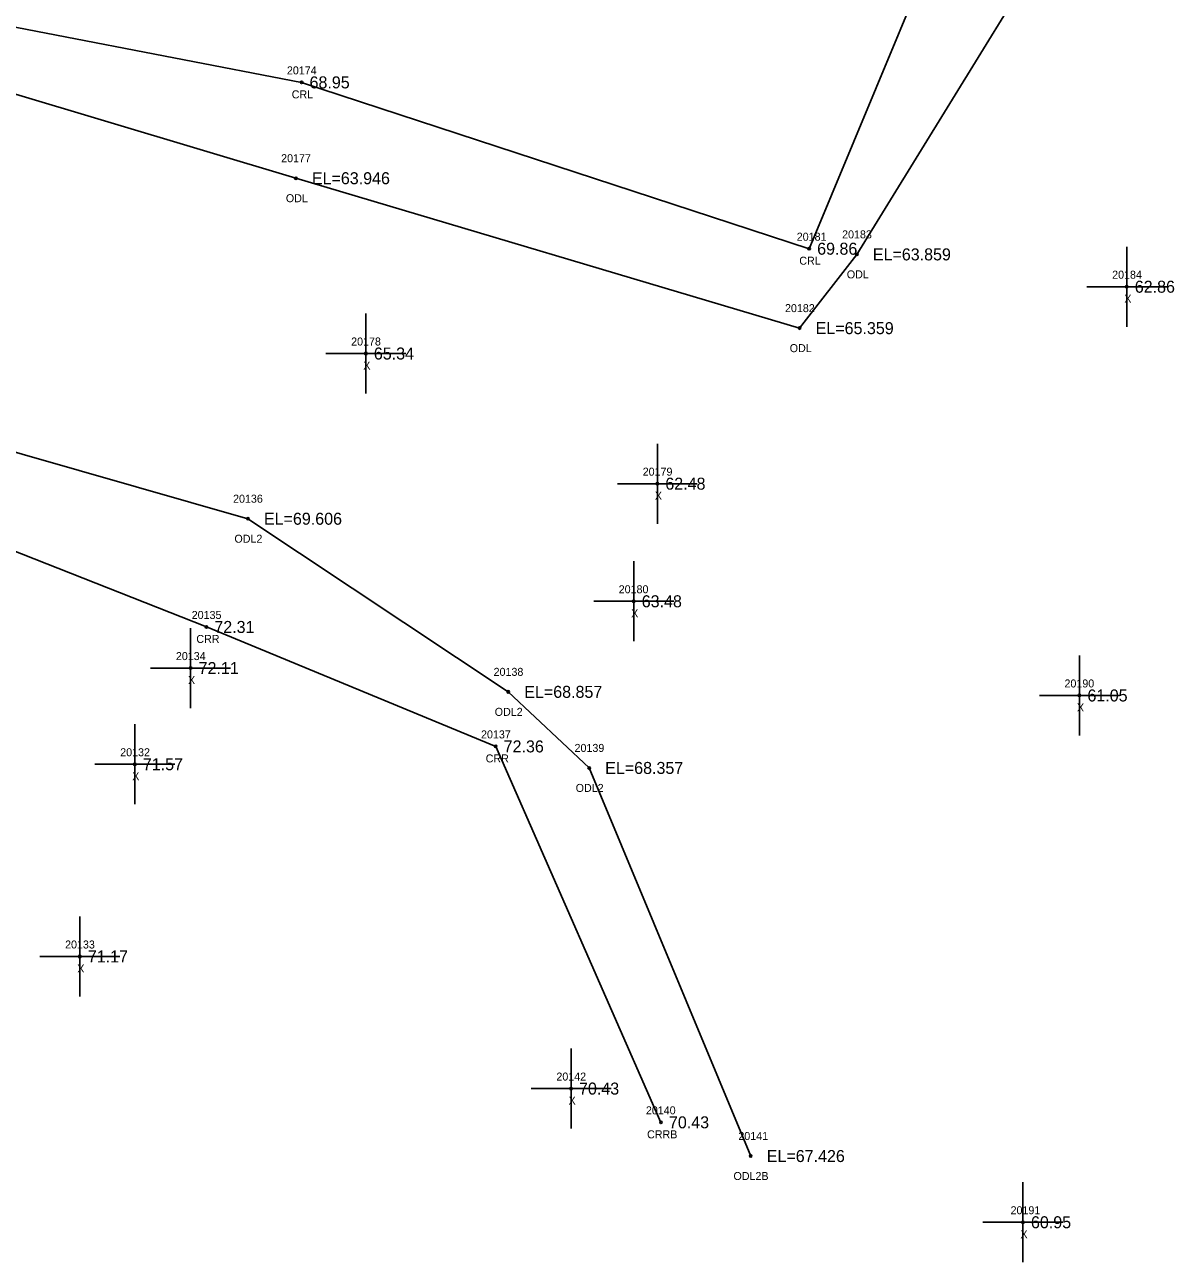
# Model space of a CAD drawing. Extents: x 2505300 to 2506184, y 912965 to 913825.
# Drawn here: x 2506017.4 to 2506161.1, y 913368 to 913522.7 of the extents above; entities that cross this region are included whole.
import ezdxf

# ---------------------------------------------------------------- set-up
doc = ezdxf.new("R2010")
doc.units = 0
for name, color, linetype in [('RD_EX_H2O', 7, 'Continuous'), ('RD_EX_H2O_txCode', 7, 'Continuous'), ('RD_EX_Misc', 7, 'Continuous'), ('RD_EX_Misc_txCode', 7, 'Continuous'), ('RD_EX_TX_H2O_ELEV', 7, 'Continuous'), ('RD_EX_TX_Misc_ELEV', 7, 'Continuous'), ('RD_SMD_Locator', 7, 'Continuous')]:
    doc.layers.add(name, color=color, linetype=linetype)

msp = doc.modelspace()

# ---------------------------------------------------------------- linework, layer by layer
at = {"layer": 'RD_EX_H2O'}
for points in [[(2505785.34, 913689.17), (2505760.31, 913663.21), (2505743.1, 913648.56), (2505723.59, 913620.14), (2505672.59, 913632.18), (2505661.09, 913622.14), (2505712.19, 913587.82), (2505787.26, 913549.76), (2505800.1, 913534.14), (2505825.87, 913510.39), (2505850.5, 913511.75), (2505883.26, 913521.88), (2505912.04, 913531.86), (2505948.81, 913534.96), (2505974.98, 913528.19), (2506003.87, 913517.71), (2506051.32, 913503.49), (2506114.3, 913484.75), (2506121.45, 913493.97), (2506156, 913550.08)], [(2505762.26, 913658.11), (2505746.15, 913644.25), (2505726.47, 913615.21), (2505674.21, 913628.01), (2505666.25, 913620.58), (2505714.6, 913592.15), (2505793.9, 913560.45), (2505801.32, 913552.8), (2505803.7, 913539.77), (2505832.63, 913516.96), (2505848.42, 913517.19), (2505881.86, 913528.44), (2505910.2, 913538.78), (2505939.3, 913544.45), (2505946.25, 913542.54), (2505974.65, 913535.18), (2506004.11, 913524.7), (2506052.03, 913515.47), (2506115.49, 913494.68), (2506138.05, 913548.89)], [(2505660.9, 913411.21), (2505684.62, 913438.72), (2505715.28, 913467.7), (2505742.46, 913486.6), (2505763.96, 913488.43), (2505794.61, 913469.83), (2505812.57, 913467.2), (2505833.64, 913450.28), (2505872.88, 913457.34), (2505893.17, 913479.86), (2505942.46, 913480.08), (2505995.98, 913475.04), (2506045.33, 913460.93), (2506077.87, 913439.29), (2506087.99, 913429.78), (2506108.19, 913381.27)], [(2505789.47, 913464.31), (2505795.69, 913463.1), (2505812.13, 913464.37), (2505832.03, 913446.73), (2505876.17, 913453.08), (2505891.76, 913474.03), (2505941.74, 913475.13), (2505995.42, 913465.05), (2506040.13, 913447.4), (2506076.3, 913432.47), (2506096.96, 913385.48)]]:
    msp.add_lwpolyline(points, dxfattribs=at)
at = {"layer": 'RD_EX_Misc'}
for p, q in [((2506155.2, 913484.93), (2506155.2, 913494.93)), ((2506150.2, 913489.93), (2506160.2, 913489.93)), ((2506060.07, 913476.58), (2506060.07, 913486.58)), ((2506055.07, 913481.58), (2506065.07, 913481.58)), ((2506096.51, 913460.31), (2506096.51, 913470.31)), ((2506091.51, 913465.31), (2506101.51, 913465.31)), ((2506093.56, 913445.61), (2506093.56, 913455.61)), ((2506088.56, 913450.61), (2506098.56, 913450.61)), ((2506038.16, 913437.26), (2506038.16, 913447.26)), ((2506149.28, 913433.84), (2506149.28, 913443.84)), ((2506033.16, 913442.26), (2506043.16, 913442.26)), ((2506144.28, 913438.84), (2506154.28, 913438.84)), ((2506031.19, 913425.24), (2506031.19, 913435.24)), ((2506026.19, 913430.24), (2506036.19, 913430.24)), ((2506024.31, 913401.21), (2506024.31, 913411.21)), ((2506019.31, 913406.21), (2506029.31, 913406.21)), ((2506085.72, 913384.7), (2506085.72, 913394.7)), ((2506080.72, 913389.7), (2506090.72, 913389.7)), ((2506142.22, 913367.99), (2506142.22, 913377.99)), ((2506137.22, 913372.99), (2506147.22, 913372.99))]:
    msp.add_line(p, q, dxfattribs=at)
at = {"layer": 'RD_SMD_Locator'}
for centre in [(2506052.03, 913515.47), (2506051.32, 913503.49), (2506115.49, 913494.68), (2506121.45, 913493.97), (2506155.2, 913489.93), (2506114.3, 913484.75), (2506060.07, 913481.58), (2506096.51, 913465.31), (2506045.33, 913460.93), (2506093.56, 913450.61), (2506040.13, 913447.4), (2506038.16, 913442.26), (2506077.87, 913439.29), (2506149.28, 913438.84), (2506076.3, 913432.47), (2506031.19, 913430.24), (2506087.99, 913429.78), (2506024.31, 913406.21), (2506085.72, 913389.7), (2506096.96, 913385.48), (2506108.19, 913381.27), (2506142.22, 913372.99)]:
    msp.add_circle(centre, 0.15, dxfattribs=at)

# ---------------------------------------------------------------- texts
at = {"layer": 'RD_EX_H2O_txCode'}
for s, p in [('20174', (2506050.2, 913516.47)), ('CRL', (2506050.8, 913513.47)), ('20177', (2506049.48, 913505.49)), ('ODL', (2506050.07, 913500.49)), ('20183', (2506119.61, 913495.97)), ('20181', (2506113.94, 913495.68)), ('CRL', (2506114.26, 913492.68)), ('ODL', (2506120.2, 913490.97)), ('20182', (2506112.47, 913486.75)), ('ODL', (2506113.06, 913481.75)), ('20136', (2506043.47, 913462.93)), ('ODL2', (2506043.64, 913457.93)), ('20135', (2506038.3, 913448.4)), ('CRR', (2506038.88, 913445.4)), ('20138', (2506076.04, 913441.29)), ('ODL2', (2506076.18, 913436.29)), ('20137', (2506074.47, 913433.47)), ('20139', (2506086.16, 913431.78)), ('CRR', (2506075.05, 913430.47)), ('ODL2', (2506086.3, 913426.78)), ('20140', (2506095.08, 913386.48)), ('CRRB', (2506095.23, 913383.48)), ('20141', (2506106.64, 913383.27)), ('ODL2B', (2506106.03, 913378.27))]:
    msp.add_text(s, height=1, dxfattribs=at).set_placement(p)
at = {"layer": 'RD_EX_Misc_txCode'}
for s, p in [('20184', (2506153.37, 913490.93)), ('X', (2506154.89, 913487.93)), ('20178', (2506058.23, 913482.58)), ('X', (2506059.75, 913479.58)), ('20179', (2506094.68, 913466.31)), ('X', (2506096.2, 913463.31)), ('20180', (2506091.68, 913451.61)), ('X', (2506093.24, 913448.61)), ('20134', (2506036.32, 913443.26)), ('X', (2506037.84, 913440.26)), ('20190', (2506147.41, 913439.84)), ('X', (2506148.97, 913436.84)), ('20132', (2506029.36, 913431.24)), ('X', (2506030.87, 913428.24)), ('20133', (2506022.47, 913407.21)), ('X', (2506023.99, 913404.21)), ('20142', (2506083.89, 913390.7)), ('X', (2506085.41, 913387.7)), ('20191', (2506140.67, 913373.99)), ('X', (2506141.91, 913370.99))]:
    msp.add_text(s, height=1, dxfattribs=at).set_placement(p)
at = {"layer": 'RD_EX_TX_H2O_ELEV'}
for s, p in [('68.95', (2506053.03, 913514.72)), ('EL=63.946', (2506053.32, 913502.74)), ('69.86', (2506116.49, 913493.93)), ('EL=63.859', (2506123.45, 913493.22)), ('EL=65.359', (2506116.3, 913484)), ('EL=69.606', (2506047.33, 913460.18)), ('72.31', (2506041.13, 913446.65)), ('EL=68.857', (2506079.87, 913438.54)), ('72.36', (2506077.3, 913431.72)), ('EL=68.357', (2506089.99, 913429.03)), ('70.43', (2506097.96, 913384.73)), ('EL=67.426', (2506110.19, 913380.52))]:
    msp.add_text(s, height=1.5, dxfattribs=at).set_placement(p)
at = {"layer": 'RD_EX_TX_Misc_ELEV'}
for s, p in [('62.86', (2506156.2, 913489.18)), ('65.34', (2506061.07, 913480.83)), ('62.48', (2506097.51, 913464.56)), ('63.48', (2506094.56, 913449.86)), ('72.11', (2506039.16, 913441.51)), ('61.05', (2506150.28, 913438.09)), ('71.57', (2506032.19, 913429.49)), ('71.17', (2506025.31, 913405.46)), ('70.43', (2506086.72, 913388.95)), ('60.95', (2506143.22, 913372.24))]:
    msp.add_text(s, height=1.5, dxfattribs=at).set_placement(p)

doc.saveas('drawing.dxf')
